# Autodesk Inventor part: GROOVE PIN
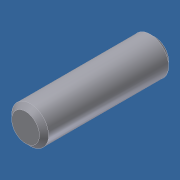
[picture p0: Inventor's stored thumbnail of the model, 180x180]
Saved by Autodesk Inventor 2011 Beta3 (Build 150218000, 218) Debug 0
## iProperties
Shininess: 64.0
Length Units: 11272
Angle Units: 11279
Time Units: 11290
Mass Units: 11286
Length Display Precision: 3
Angle Display Precision: 2
Compacted: True
Part Number: GROOVE PIN
Document SubType Name: Modeling
Created: 2003-11
Designer: Autodesk, Inc.
Manufacturer: Standard
Standards Organization: Custom
Mass: 5.44307 g
Surface Area: 4.86691 cm^2
Volume: 0.692502 cm^3
Density: 7.86 g/cm^3
Material: Steel, Mild
Density: 0.0
Volumn: 0.0
Area: 0.0
PropertySet Name: Model Information
Control State: 0
Master: False
Checked Out: False
Author: Autodesk, Inc.
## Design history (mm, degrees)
sketch "Sketch1"
  geometry: C1 r 3.175 at (0, 0); 1 further point
  constraints: 1 centre point, 1 coincident
  dimensions: "d0" = 6.35 diameter of C1
extrude "Extrusion1" new body sketch "Sketch1" distance "d1" = 22.225; taper "d2" = 0 deg
chamfer "Chamfer1" distance "d3" = 0.7874; stored, may be unused: second distance "d4" = 3.175, angle "d5" = 45 deg
body "Solid1"
